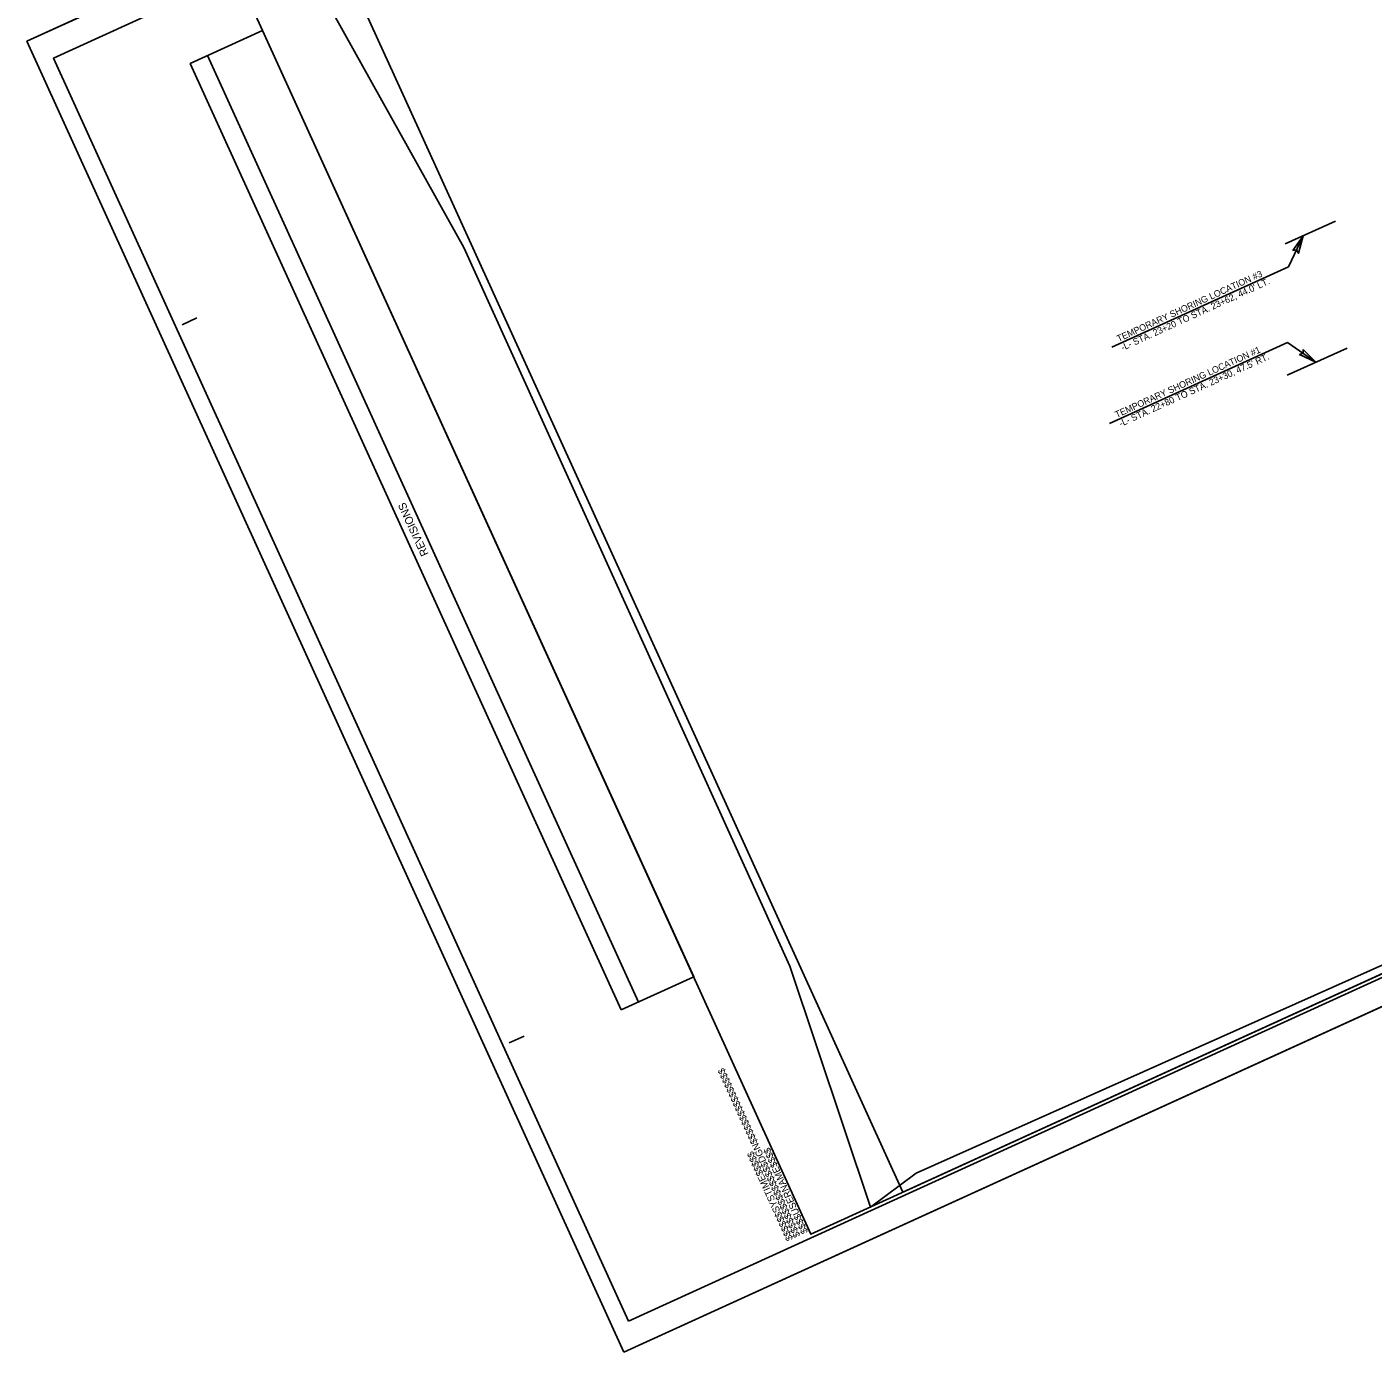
# Model space of a CAD drawing. Extents: x 2247910 to 2249896, y 662531 to 664266.
# Drawn here: x 2247910 to 2248933, y 662531 to 663539 of the extents above; entities that cross this region are included whole.
import ezdxf

# ---------------------------------------------------------------- set-up
doc = ezdxf.new("R2010")
doc.units = 0
for name, color, linetype in [('Prop Temporary Shoring', 7, 'Continuous'), ('Prop Temporary Shoring Leader Line', 7, 'Continuous'), ('Prop Terminator CELL', 7, 'Continuous'), ('Sheet Block Revision CELL', 7, 'Continuous'), ('Sheet Clip Boundary CELL', 7, 'Continuous'), ('Sheet Cutting Line CELL', 7, 'Continuous'), ('Sheet Layout Plan Border', 7, 'Continuous'), ('Sheet Plan CELL', 7, 'Continuous'), ('Sheet Plan Layout CELL', 7, 'Continuous'), ('Sheet Plot Border Inside CELL', 7, 'Continuous'), ('Sheet Plot Border Outside CELL', 7, 'Continuous')]:
    doc.layers.add(name, color=color, linetype=linetype)

msp = doc.modelspace()

# ---------------------------------------------------------------- linework, layer by layer
at = {"layer": 'Prop Temporary Shoring'}
for p, q in [((2248866.5, 663373.7), (2248904.7, 663391.1)), ((2248867.9, 663273.9), (2248913.5, 663294.6))]:
    msp.add_line(p, q, dxfattribs=at)
at = {"layer": 'Prop Temporary Shoring Leader Line'}
for p, q in [((2248869, 663356.4), (2248880.1, 663379.9)), ((2248734.6, 663295.2), (2248869, 663356.4)), ((2248732.8, 663237.2), (2248868.2, 663298.9)), ((2248868.2, 663298.9), (2248889.9, 663283.8))]:
    msp.add_line(p, q, dxfattribs=at)
at = {"layer": 'Prop Terminator CELL'}
for points in [[(2248872.2, 663368.7), (2248880.1, 663379.9), (2248876.5, 663366.6), (2248875.1, 663369.2)], [(2248880.1, 663293.5), (2248889.9, 663283.8), (2248877.4, 663289.6), (2248880.2, 663290.6)]]:
    msp.add_lwpolyline(points, close=True, dxfattribs=at)
at = {"layer": 'Sheet Block Revision CELL'}
msp.add_line((2248374.7, 662797.4), (2248046.9, 663516.9), dxfattribs=at)
msp.add_lwpolyline([(2248361.5, 662791.4), (2248033.7, 663510.8), (2248088.7, 663536), (2248416.6, 662816.5)], close=True, dxfattribs=at)
at = {"layer": 'Sheet Clip Boundary CELL'}
msp.add_lwpolyline([(2248241.7, 663371.1), (2248489.8, 662824.8), (2248551.2, 662641.6), (2248585.9, 662667.3), (2249638.1, 663136.9), (2249825.2, 663222.1), (2249759.4, 663344.8), (2249697.6, 663317.2), (2249673.4, 663362.4), (2249425.3, 663908.7), (2249477.5, 663985.1), (2249333.3, 663919.4), (2249245.6, 664111.9), (2248806.2, 663911.3), (2248826.4, 663857), (2248820.5, 663848.4), (2248540.8, 663728.2), (2248517.3, 663777.9), (2248115.8, 663597.1)], close=True, dxfattribs=at)
at = {"layer": 'Sheet Cutting Line CELL'}
for p, q in [((2249441.4, 664225.8), (2247909.5, 663527.8)), ((2247909.5, 663527.8), (2248363.6, 662531.3)), ((2248363.6, 662531.3), (2249895.5, 663229.4))]:
    msp.add_line(p, q, dxfattribs=at)
at = {"layer": 'Sheet Layout Plan Border'}
msp.add_lwpolyline([(2248198.1, 663481.5), (2248575.8, 662652.8), (2249849.7, 663233.3), (2249502.1, 663996.3), (2249329.8, 663917.8), (2249242.1, 664110.3), (2248140.4, 663608.2)], close=True, dxfattribs=at)
at = {"layer": 'Sheet Plan CELL'}
for p, q in [((2248027.5, 663312.3), (2248038.8, 663317.5)), ((2248276.3, 662766.3), (2248287.7, 662771.5)), ((2248505.7, 662620.9), (2248505.7, 662620.9))]:
    msp.add_line(p, q, dxfattribs=at)
for points in [[(2249435.3, 664198.3), (2248070.3, 663576.3), (2248505.7, 662620.9), (2249870.7, 663242.8)], [(2248505.7, 662620.9), (2248070.3, 663576.3), (2249253.3, 664115.4), (2249268.8, 664081.2), (2249359.9, 664122.7), (2249406.5, 664020.3), (2249497.5, 664061.8), (2249870.7, 663242.8)]]:
    msp.add_lwpolyline(points, close=True, dxfattribs=at)
at = {"layer": 'Sheet Plan Layout CELL'}
msp.add_lwpolyline([(2248070.3, 663576.3), (2248505.7, 662620.9), (2249870.7, 663242.8), (2249523, 664005.9), (2249305.3, 663906.7), (2249217.6, 664099.1)], close=True, dxfattribs=at)
at = {"layer": 'Sheet Plot Border Inside CELL'}
msp.add_lwpolyline([(2248367.1, 662554.9), (2249883.1, 663245.8), (2249445.6, 664205.8), (2247929.6, 663514.9)], close=True, dxfattribs=at)
at = {"layer": 'Sheet Plot Border Outside CELL'}
msp.add_lwpolyline([(2248363.6, 662531.3), (2249895.5, 663229.4), (2249441.4, 664225.8), (2247909.5, 663527.8)], close=True, dxfattribs=at)

# ---------------------------------------------------------------- texts
at = {"layer": 'Prop Temporary Shoring'}
for s, p in [('TEMPORARY SHORING LOCATION #3', (2248739.8, 663299.2)), ("-L- STA. 23+20 TO STA. 23+62, 44.0' LT.", (2248742.9, 663292.4)), ('TEMPORARY SHORING LOCATION #1', (2248738.4, 663241.4)), ("-L- STA. 22+80 TO STA. 23+30, 47.5' RT.", (2248741.5, 663234.6))]:
    msp.add_text(s, height=5, rotation=24.4979, dxfattribs=at).set_placement(p)
at = {"layer": 'Sheet Block Revision CELL'}
msp.add_text('REVISIONS', height=6, rotation=114.4979, dxfattribs=at).set_placement((2248215.1, 663138))
at = {"layer": 'Sheet Plan CELL'}
for s, p in [('$$$$$$$$$$$$$$$$DGN$$$$$$$$$$$$$$$$', (2248497.8, 662619.8)), ('$$$$USERNAME$$$$', (2248503.7, 662622.6)), ('$$$$$$SYSTIME$$$$$', (2248492.3, 662617.3))]:
    msp.add_text(s, height=5.25, rotation=114.4979, dxfattribs=at).set_placement(p)

doc.saveas('drawing.dxf')
